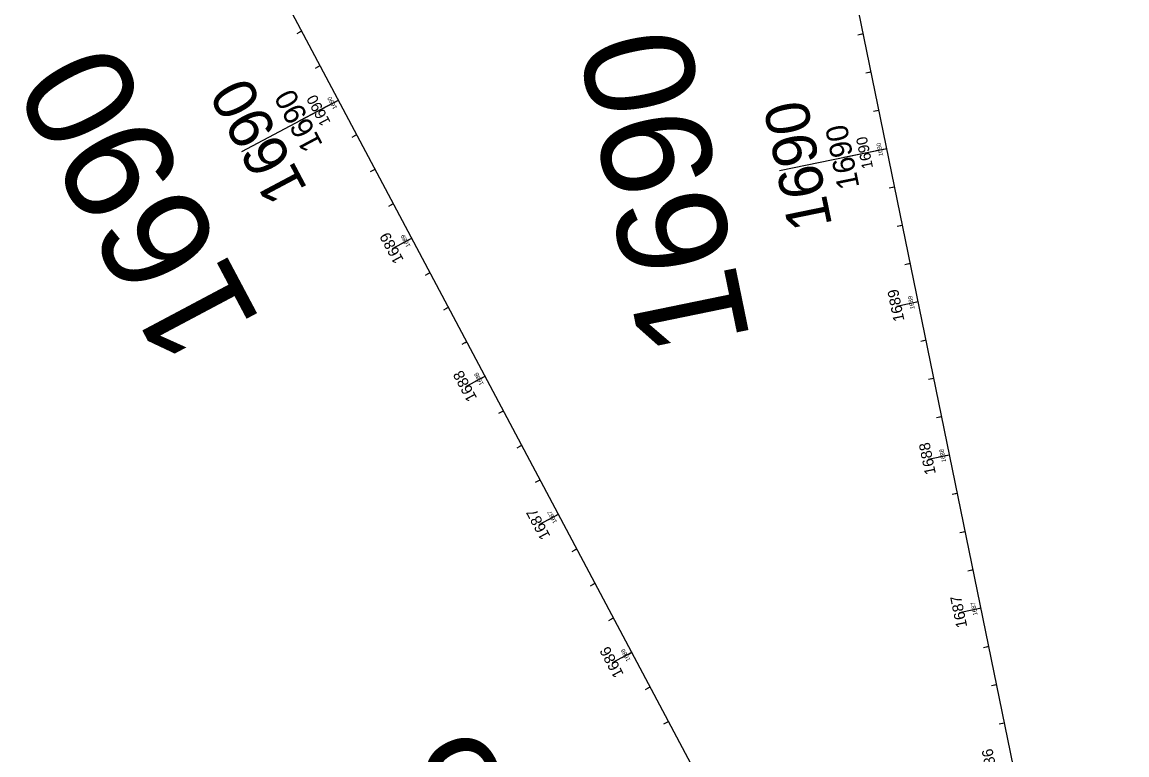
# Model space of a CAD drawing. Extents: x 353835 to 363333, y 126218 to 205387.
# Drawn here: x 361618 to 362324, y 127866 to 128334 of the extents above; entities that cross this region are included whole.
import ezdxf

# ---------------------------------------------------------------- set-up
doc = ezdxf.new("R2010")
doc.units = 0
for name, color, linetype in [('P_ALI_100_Sta', 7, 'Continuous'), ('P_ALI_100_Tic', 7, 'Continuous'), ('P_ALI_20', 7, 'Continuous'), ('P_ALI_200_Sta', 7, 'Continuous'), ('P_ALI_200_Tic', 7, 'Continuous'), ('P_ALI_20_Sta', 7, 'Continuous'), ('P_ALI_20_Tic', 7, 'Continuous'), ('P_ALI_500_Sta', 7, 'Continuous'), ('P_ALI_50_Sta', 7, 'Continuous'), ('P_ALI_50_Tic', 7, 'Continuous')]:
    doc.layers.add(name, color=color, linetype=linetype)

msp = doc.modelspace()

# ---------------------------------------------------------------- linework, layer by layer
for points in [[(362190.95, 128155.68), (362190.97, 128155.69)], [(362211.06, 128057.73), (362211.08, 128057.73)], [(362231.16, 127959.77), (362231.18, 127959.77)]]:
    msp.add_lwpolyline(points)
at = {"layer": 'P_ALI_100_Tic'}
for points in [[(361758.33, 128251.79), (361820.15, 128284.63)], [(361807.79, 128278.06), (361820.15, 128284.63)], [(362102.28, 128239.57), (362170.85, 128253.64)], [(362157.14, 128250.83), (362170.85, 128253.64)], [(361860.89, 128193.04), (361867.07, 128196.32)], [(362184.1, 128154.28), (362190.96, 128155.69)], [(361907.8, 128104.73), (361913.99, 128108.01)], [(362204.21, 128056.32), (362211.07, 128057.73)], [(361954.72, 128016.42), (361960.9, 128019.7)], [(362224.32, 127958.36), (362231.17, 127959.77)], [(362001.64, 127928.11), (362007.82, 127931.39)]]:
    msp.add_lwpolyline(points, dxfattribs=at)
at = {"layer": 'P_ALI_20'}
for p, q in [((362324.47, 127505.25), (361863.67, 129750.1)), ((362054.39, 127843.73), (361705.87, 128499.72))]:
    msp.add_line(p, q, dxfattribs=at)
at = {"layer": 'P_ALI_200_Tic'}
for points in [[(361795.42, 128271.49), (361820.15, 128284.63)], [(362143.42, 128248.01), (362170.85, 128253.64)], [(361854.7, 128189.75), (361867.07, 128196.32)], [(362177.24, 128152.87), (362190.96, 128155.69)], [(361901.62, 128101.44), (361913.99, 128108.01)], [(362197.35, 128054.91), (362211.07, 128057.73)], [(361948.54, 128013.13), (361960.9, 128019.7)], [(362217.46, 127956.96), (362231.17, 127959.77)], [(361995.46, 127924.82), (362007.82, 127931.39)]]:
    msp.add_lwpolyline(points, dxfattribs=at)
at = {"layer": 'P_ALI_20_Tic'}
for points in [[(361795.45, 128328.13), (361796.69, 128328.79)], [(362154.4, 128326.83), (362155.77, 128327.11)], [(361807.18, 128306.05), (361808.42, 128306.71)], [(362159.42, 128302.34), (362160.8, 128302.62)], [(361817.68, 128283.32), (361820.15, 128284.63)], [(362164.45, 128277.85), (362165.82, 128278.13)], [(361830.64, 128261.9), (361831.88, 128262.55)], [(362168.11, 128253.08), (362170.85, 128253.64)], [(361842.37, 128239.82), (361843.61, 128240.48)], [(362174.51, 128228.87), (362175.88, 128229.15)], [(361854.1, 128217.74), (361855.34, 128218.4)], [(362179.53, 128204.38), (362180.9, 128204.66)], [(361864.59, 128195.01), (361867.07, 128196.32)], [(362184.56, 128179.89), (362185.93, 128180.18)], [(361877.56, 128173.59), (361878.8, 128174.24)], [(362188.21, 128155.12), (362190.96, 128155.69)], [(361889.29, 128151.51), (361890.53, 128152.17)], [(361901.02, 128129.43), (361902.26, 128130.09)], [(362194.61, 128130.92), (362195.98, 128131.2)], [(361911.51, 128106.7), (361913.99, 128108.01)], [(362199.64, 128106.43), (362201.01, 128106.71)], [(361924.48, 128085.28), (361925.71, 128085.93)], [(362204.67, 128081.94), (362206.04, 128082.22)], [(361936.21, 128063.2), (361937.44, 128063.86)], [(362208.32, 128057.17), (362211.07, 128057.73)], [(361947.94, 128041.12), (361949.17, 128041.78)], [(362214.72, 128032.96), (362216.09, 128033.24)], [(361958.43, 128018.39), (361960.9, 128019.7)], [(362219.75, 128008.47), (362221.12, 128008.75)], [(361971.4, 127996.97), (361972.63, 127997.62)], [(362224.78, 127983.98), (362226.15, 127984.26)], [(361983.13, 127974.89), (361984.36, 127975.55)], [(362228.43, 127959.21), (362231.17, 127959.77)], [(361994.86, 127952.81), (361996.09, 127953.47)], [(362005.35, 127930.08), (362007.82, 127931.39)], [(362234.83, 127935), (362236.2, 127935.28)], [(362018.31, 127908.66), (362019.55, 127909.31)], [(362239.86, 127910.51), (362241.23, 127910.79)], [(362030.04, 127886.58), (362031.28, 127887.24)], [(362244.88, 127886.02), (362246.25, 127886.3)]]:
    msp.add_lwpolyline(points, dxfattribs=at)
at = {"layer": 'P_ALI_50_Tic'}
for points in [[(361793.6, 128327.14), (361796.69, 128328.79)], [(361793.6, 128327.14), (361796.69, 128328.79)], [(362152.34, 128326.41), (362155.77, 128327.11)], [(361805.33, 128305.07), (361808.42, 128306.71)], [(361805.33, 128305.07), (361808.42, 128306.71)], [(362157.37, 128301.92), (362160.8, 128302.62)], [(361813.97, 128281.35), (361820.15, 128284.63)], [(361813.97, 128281.35), (361820.15, 128284.63)], [(362162.39, 128277.43), (362165.82, 128278.13)], [(361828.79, 128260.91), (361831.88, 128262.55)], [(361828.79, 128260.91), (361831.88, 128262.55)], [(362163.99, 128252.24), (362170.85, 128253.64)], [(361840.52, 128238.83), (361843.61, 128240.48)], [(361840.52, 128238.83), (361843.61, 128240.48)], [(362172.45, 128228.45), (362175.88, 128229.15)], [(361852.25, 128216.76), (361855.34, 128218.4)], [(361852.25, 128216.76), (361855.34, 128218.4)], [(362177.48, 128203.96), (362180.9, 128204.66)], [(361860.89, 128193.04), (361867.07, 128196.32)], [(361860.89, 128193.04), (361867.07, 128196.32)], [(362182.5, 128179.47), (362185.93, 128180.18)], [(361875.71, 128172.6), (361878.8, 128174.24)], [(361875.71, 128172.6), (361878.8, 128174.24)], [(362184.1, 128154.28), (362190.96, 128155.69)], [(361887.44, 128150.52), (361890.53, 128152.17)], [(361887.44, 128150.52), (361890.53, 128152.17)], [(361899.16, 128128.45), (361902.26, 128130.09)], [(361899.16, 128128.45), (361902.26, 128130.09)], [(362192.56, 128130.49), (362195.98, 128131.2)], [(361907.8, 128104.73), (361913.99, 128108.01)], [(361907.8, 128104.73), (361913.99, 128108.01)], [(362197.58, 128106), (362201.01, 128106.71)], [(361922.62, 128084.29), (361925.71, 128085.93)], [(361922.62, 128084.29), (361925.71, 128085.93)], [(362202.61, 128081.51), (362206.04, 128082.22)], [(361934.35, 128062.21), (361937.44, 128063.86)], [(361934.35, 128062.21), (361937.44, 128063.86)], [(362204.21, 128056.32), (362211.07, 128057.73)], [(361946.08, 128040.14), (361949.17, 128041.78)], [(361946.08, 128040.14), (361949.17, 128041.78)], [(362212.66, 128032.54), (362216.09, 128033.24)], [(361954.72, 128016.42), (361960.9, 128019.7)], [(361954.72, 128016.42), (361960.9, 128019.7)], [(362217.69, 128008.05), (362221.12, 128008.75)], [(361969.54, 127995.98), (361972.63, 127997.62)], [(361969.54, 127995.98), (361972.63, 127997.62)], [(362222.72, 127983.56), (362226.15, 127984.26)], [(361981.27, 127973.9), (361984.36, 127975.55)], [(361981.27, 127973.9), (361984.36, 127975.55)], [(362224.32, 127958.36), (362231.17, 127959.77)], [(361993, 127951.83), (361996.09, 127953.47)], [(361993, 127951.83), (361996.09, 127953.47)], [(362001.64, 127928.11), (362007.82, 127931.39)], [(362001.64, 127928.11), (362007.82, 127931.39)], [(362232.77, 127934.58), (362236.2, 127935.28)], [(362016.46, 127907.67), (362019.55, 127909.31)], [(362016.46, 127907.67), (362019.55, 127909.31)], [(362237.8, 127910.09), (362241.23, 127910.79)], [(362028.19, 127885.59), (362031.28, 127887.24)], [(362028.19, 127885.59), (362031.28, 127887.24)], [(362242.83, 127885.6), (362246.25, 127886.3)]]:
    msp.add_lwpolyline(points, dxfattribs=at)

# ---------------------------------------------------------------- texts
at = {"layer": 'P_ALI_100_Sta'}
for rotation, p in [(117.98126, (361810.39, 128256.1)), (101.60009, (362153.44, 128229.03))]:
    msp.add_text('1690', height=14, rotation=rotation, dxfattribs=at).set_placement(p)
at = {"layer": 'P_ALI_200_Sta'}
for rotation, p in [(117.98126, (361800.64, 128227.58)), (101.60009, (362136.04, 128204.41))]:
    msp.add_text('1690', height=28, rotation=rotation, dxfattribs=at).set_placement(p)
at = {"layer": 'P_ALI_20_Sta'}
for s, rotation, p in [('1690', 117.98126, (361819.36, 128279.55)), ('1690', 101.60009, (362168.66, 128248.99)), ('1689', 117.98126, (361866.22, 128191.35)), ('1689', 101.60009, (362188.74, 128151.16)), ('1688', 117.98126, (361913.14, 128103.04)), ('1688', 101.60009, (362208.85, 128053.2)), ('1687', 117.98126, (361960.06, 128014.73)), ('1687', 101.60009, (362228.96, 127955.24)), ('1686', 117.98126, (362006.97, 127926.43))]:
    msp.add_text(s, height=2.8, rotation=rotation, dxfattribs=at).set_placement(p)
at = {"layer": 'P_ALI_500_Sta'}
for s, rotation, p in [('1690', 101.60009, (362083.82, 128130.56)), ('1690', 117.98126, (361771.37, 128142)), ('1685', 117.96369, (362004.36, 127703.38))]:
    msp.add_text(s, height=70, rotation=rotation, dxfattribs=at).set_placement(p)
at = {"layer": 'P_ALI_50_Sta'}
for s, rotation, p in [('1690', 117.98126, (361815.27, 128270.37)), ('1690', 117.98126, (361815.27, 128270.37)), ('1690', 101.60009, (362162.15, 128241.34)), ('1689', 117.98126, (361862.03, 128182.35)), ('1689', 117.98126, (361862.03, 128182.35)), ('1689', 101.60009, (362182.19, 128143.7)), ('1688', 117.98126, (361908.95, 128094.04)), ('1688', 117.98126, (361908.95, 128094.04)), ('1688', 101.60009, (362202.3, 128045.74)), ('1687', 117.98126, (361955.87, 128005.73)), ('1687', 117.98126, (361955.87, 128005.73)), ('1687', 101.60009, (362222.4, 127947.79)), ('1686', 117.98126, (362002.78, 127917.44)), ('1686', 117.98126, (362002.78, 127917.44)), ('1686', 101.60009, (362242.51, 127849.86))]:
    msp.add_text(s, height=7, rotation=rotation, dxfattribs=at).set_placement(p)

doc.saveas('drawing.dxf')
